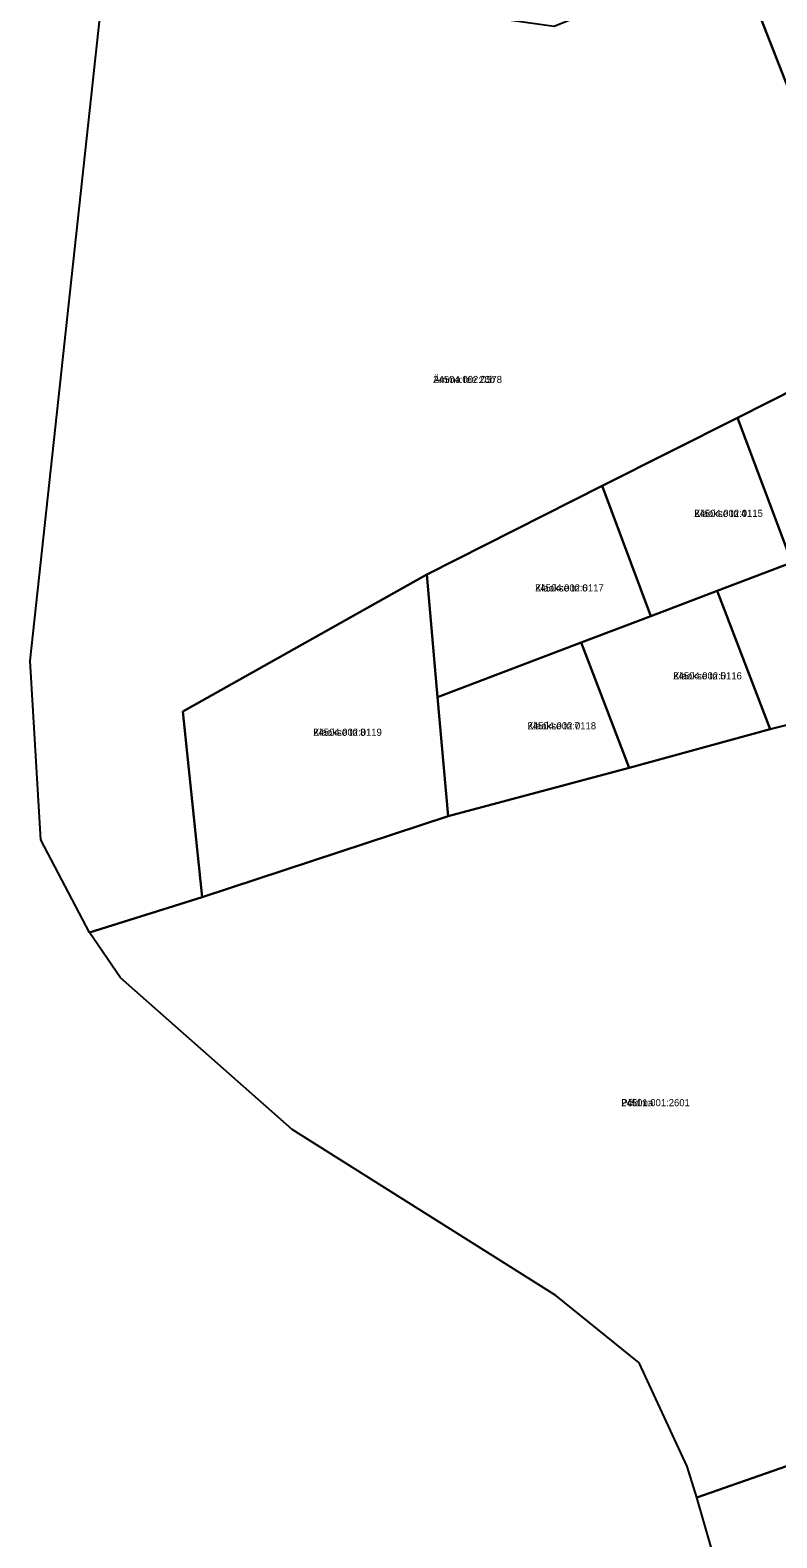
# Model space of a CAD drawing. Extents: x 551291 to 575799, y 6581704 to 6610137.
# Drawn here: x 551549.8 to 551707.6, y 6590972.2 to 6591290.7 of the extents above; entities that cross this region are included whole.
import ezdxf

# ---------------------------------------------------------------- set-up
doc = ezdxf.new("R2010")
doc.units = 0
for name, color, linetype in [('L_AADRESS', 7, 'Continuous'), ('PIIR', 7, 'Continuous'), ('TUNNUS', 7, 'Continuous')]:
    doc.layers.add(name, color=color, linetype=linetype)

msp = doc.modelspace()

# ---------------------------------------------------------------- linework, layer by layer
at = {"layer": 'PIIR'}
for points in [[(551592.26, 6591318.17), (551621.99, 6591332.29), (551623.99, 6591329.04), (551632.52, 6591311.28), (551638.82, 6591301.29), (551648.47, 6591293.24), (551660.58, 6591291.58), (551671.63, 6591296.03), (551697.08, 6591311.6), (551731.03, 6591224.85), (551725.67, 6591222.15), (551699.31, 6591208.85), (551670.73, 6591194.44), (551633.68, 6591175.75), (551582.09, 6591146.82), (551586.14, 6591107.57), (551562.34, 6591100.09), (551552.1, 6591119.71), (551549.82, 6591157.52), (551565.91, 6591305.65), (551578.48, 6591311.61)], [(551699.31, 6591208.85), (551725.67, 6591222.15), (551727.38, 6591217.45), (551732.76, 6591220.16), (551743.63, 6591190.71), (551720.15, 6591181.8), (551710.76, 6591178.24)], [(551670.73, 6591194.44), (551699.31, 6591208.85), (551710.76, 6591178.24), (551695.02, 6591172.27), (551681, 6591166.95)], [(551633.68, 6591175.75), (551670.73, 6591194.44), (551681, 6591166.95), (551666.25, 6591161.35), (551635.94, 6591149.85)], [(551706.24, 6591143.05), (551695.02, 6591172.27), (551710.76, 6591178.24), (551720.15, 6591181.8), (551732.35, 6591150.09), (551718.14, 6591146.05)], [(551582.09, 6591146.82), (551633.68, 6591175.75), (551635.94, 6591149.85), (551638.15, 6591124.7), (551586.14, 6591107.57)], [(551666.25, 6591161.35), (551681, 6591166.95), (551695.02, 6591172.27), (551706.24, 6591143.05), (551676.44, 6591134.9)], [(551635.94, 6591149.85), (551666.25, 6591161.35), (551676.44, 6591134.9), (551638.15, 6591124.7)], [(551568.89, 6591090.56), (551562.34, 6591100.09), (551586.14, 6591107.57), (551638.15, 6591124.7), (551676.44, 6591134.9), (551706.24, 6591143.05), (551718.14, 6591146.05), (551767.4, 6591017.71), (551740.16, 6590998.04), (551718.56, 6590990.49), (551690.68, 6590980.77), (551688.64, 6590987.27), (551678.52, 6591009.23), (551660.89, 6591023.42), (551605.18, 6591058.47)], [(551698.09, 6590955.05), (551690.68, 6590980.77), (551718.56, 6590990.49), (551740.16, 6590998.04), (551767.4, 6591017.71), (551786.76, 6591031.59), (551794.54, 6591035.23), (551819.61, 6590970.63), (551815.16, 6590969.32), (551797.8, 6590962.57), (551787.92, 6590905.1), (551782.6, 6590874.19), (551777.32, 6590843.5), (551770.75, 6590805.28), (551767.78, 6590787.98), (551772.28, 6590756.35), (551710.96, 6590747.66), (551655.02, 6590739.72), (551623.91, 6590735.04), (551640.06, 6590768.98), (551673.7, 6590805.26), (551693.9, 6590853.77), (551696.13, 6590876.83)]]:
    msp.add_lwpolyline(points, close=True, dxfattribs=at)
msp.add_lwpolyline([(551731.03, 6591224.85), (551697.08, 6591311.6)], dxfattribs=at)

# ---------------------------------------------------------------- texts
at = {"layer": 'L_AADRESS'}
for s, p in [('Ämma tee 20b', (551635.03, 6591216.19)), ('Klaokse tn 4', (551690.16, 6591187.9)), ('Klaokse tn 6', (551656.53, 6591172.15)), ('Klaokse tn 5', (551685.72, 6591153.58)), ('Klaokse tn 7', (551654.92, 6591143.03)), ('Klaokse tn 8', (551609.64, 6591141.66)), ('Põldma', (551674.73, 6591063.41))]:
    msp.add_text(s, height=1.5, dxfattribs=at).set_placement(p)
at = {"layer": 'TUNNUS'}
for s, p in [('24504:002:0578', (551635.03, 6591216.19)), ('24504:002:0115', (551690.16, 6591187.9)), ('24504:002:0117', (551656.53, 6591172.15)), ('24504:002:0116', (551685.72, 6591153.58)), ('24504:002:0118', (551654.92, 6591143.03)), ('24504:002:0119', (551609.64, 6591141.66)), ('24501:001:2601', (551674.73, 6591063.41))]:
    msp.add_text(s, height=1.5, dxfattribs=at).set_placement(p)

doc.saveas('drawing.dxf')
